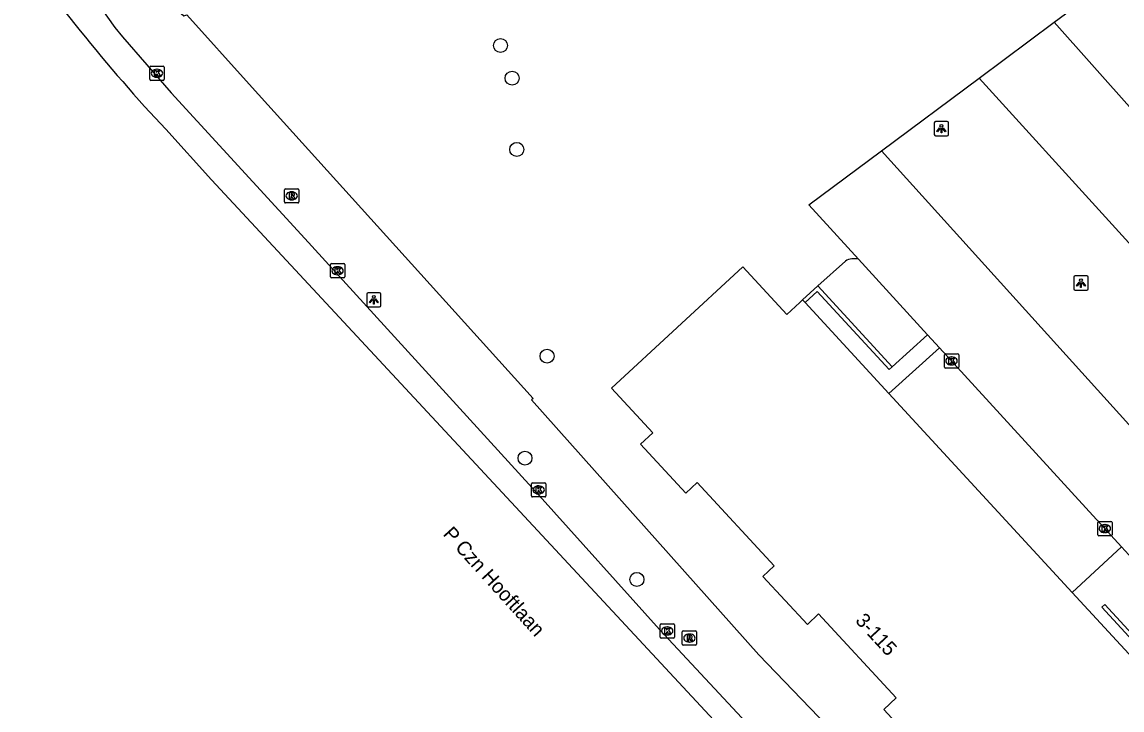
# Model space of a CAD drawing. Extents: x 161087 to 161922, y 382574 to 383873.
# Drawn here: x 161573.6 to 161650.7, y 382684.2 to 382732.3 of the extents above; entities that cross this region are included whole.
import ezdxf

# ---------------------------------------------------------------- set-up
doc = ezdxf.new("R2010")
doc.units = 0
for name, color, linetype in [('IMGEO_Boom', 7, 'Continuous'), ('IMGEO_Groenvoorziening', 7, 'Continuous'), ('IMGEO_Kolk', 7, 'Continuous'), ('IMGEO_Lichtpunt', 7, 'Continuous'), ('IMGEO_Muur', 7, 'Continuous'), ('IMGEO_Openbare_ruimte_label', 7, 'Continuous'), ('IMGEO_Pand', 7, 'Continuous'), ('IMGEO_Pand_nummerreeks', 7, 'Continuous'), ('IMGEO_Parkeervlak_open', 7, 'Continuous'), ('IMGEO_Rijbaan_lokaal_gesloten', 7, 'Continuous'), ('IMGEO_Rijbaan_lokaal_open', 7, 'Continuous'), ('IMGEO_Rioolput', 7, 'Continuous'), ('IMGEO_Voetpad_open', 7, 'Continuous')]:
    doc.layers.add(name, color=color, linetype=linetype)

msp = doc.modelspace()

# ---------------------------------------------------------------- linework, layer by layer
at = {"layer": 'IMGEO_Boom'}
for centre in [(161607.142, 382730.699), (161607.958, 382728.415), (161608.285, 382723.426), (161610.405, 382708.942), (161608.861, 382701.802), (161616.697, 382693.31)]:
    msp.add_circle(centre, 0.489, dxfattribs=at)
at = {"layer": 'IMGEO_Groenvoorziening'}
msp.add_lwpolyline([(161629.361, 382713.862), (161631.288, 382715.608)], dxfattribs=at)
msp.add_arc((161631.903, 382714.542), 1.231, 75.94681, 119.99733, dxfattribs=at)
at = {"layer": 'IMGEO_Kolk'}
for p, q in [((161582.598, 382728.335), (161582.598, 382729.187)), ((161582.673, 382729.261), (161583.525, 382729.261)), ((161583.599, 382729.187), (161583.599, 382728.335)), ((161583.109, 382728.481), (161583.084, 382728.481)), ((161583.086, 382729.041), (161583.111, 382729.041)), ((161583.525, 382728.261), (161582.673, 382728.261)), ((161595.241, 382714.502), (161595.241, 382715.354)), ((161595.316, 382715.428), (161596.168, 382715.428)), ((161595.729, 382715.208), (161595.754, 382715.208)), ((161596.242, 382715.354), (161596.242, 382714.502)), ((161595.752, 382714.648), (161595.727, 382714.648)), ((161596.168, 382714.428), (161595.316, 382714.428)), ((161638.294, 382709.109), (161639.146, 382709.109)), ((161638.219, 382708.183), (161638.219, 382709.035)), ((161638.73, 382708.329), (161638.705, 382708.329)), ((161638.707, 382708.889), (161638.732, 382708.889)), ((161639.22, 382709.035), (161639.22, 382708.183)), ((161639.146, 382708.109), (161638.294, 382708.109)), ((161609.316, 382699.156), (161609.316, 382700.008)), ((161609.391, 382700.082), (161610.243, 382700.082)), ((161609.804, 382699.862), (161609.829, 382699.862)), ((161610.317, 382700.008), (161610.317, 382699.156)), ((161610.243, 382699.082), (161609.391, 382699.082)), ((161609.827, 382699.302), (161609.802, 382699.302)), ((161648.954, 382696.443), (161648.954, 382697.295)), ((161649.029, 382697.369), (161649.881, 382697.369)), ((161649.442, 382697.149), (161649.467, 382697.149)), ((161649.955, 382697.295), (161649.955, 382696.443)), ((161649.881, 382696.369), (161649.029, 382696.369)), ((161649.465, 382696.589), (161649.44, 382696.589)), ((161618.319, 382689.273), (161618.319, 382690.125)), ((161618.394, 382690.199), (161619.246, 382690.199)), ((161618.807, 382689.979), (161618.832, 382689.979)), ((161619.32, 382690.125), (161619.32, 382689.273)), ((161619.246, 382689.199), (161618.394, 382689.199)), ((161618.83, 382689.419), (161618.805, 382689.419))]:
    msp.add_line(p, q, dxfattribs=at)
for points in [[(161582.598, 382728.335), (161582.598, 382729.187)], [(161582.673, 382729.261), (161583.525, 382729.261)], [(161583.599, 382729.187), (161583.599, 382728.335)], [(161582.919, 382728.961), (161583.042, 382728.961), (161583.042, 382728.81), (161583.172, 382728.961), (161583.336, 382728.961), (161583.19, 382728.81), (161583.343, 382728.561), (161583.191, 382728.561), (161583.106, 382728.725), (161583.042, 382728.658), (161583.042, 382728.561), (161582.919, 382728.561), (161582.919, 382728.961)], [(161583.525, 382728.261), (161582.673, 382728.261)], [(161595.241, 382714.502), (161595.241, 382715.354)], [(161595.316, 382715.428), (161596.168, 382715.428)], [(161596.242, 382715.354), (161596.242, 382714.502)], [(161595.562, 382715.128), (161595.685, 382715.128), (161595.685, 382714.977), (161595.815, 382715.128), (161595.979, 382715.128), (161595.833, 382714.977), (161595.986, 382714.728), (161595.834, 382714.728), (161595.749, 382714.892), (161595.685, 382714.825), (161595.685, 382714.728), (161595.562, 382714.728), (161595.562, 382715.128)], [(161596.168, 382714.428), (161595.316, 382714.428)], [(161638.294, 382709.109), (161639.146, 382709.109)], [(161638.219, 382708.183), (161638.219, 382709.035)], [(161638.54, 382708.809), (161638.663, 382708.809), (161638.663, 382708.658), (161638.793, 382708.809), (161638.957, 382708.809), (161638.811, 382708.658), (161638.964, 382708.409), (161638.812, 382708.409), (161638.727, 382708.573), (161638.663, 382708.506), (161638.663, 382708.409), (161638.54, 382708.409), (161638.54, 382708.809)], [(161639.22, 382709.035), (161639.22, 382708.183)], [(161639.146, 382708.109), (161638.294, 382708.109)], [(161609.316, 382699.156), (161609.316, 382700.008)], [(161609.391, 382700.082), (161610.243, 382700.082)], [(161610.317, 382700.008), (161610.317, 382699.156)], [(161610.243, 382699.082), (161609.391, 382699.082)], [(161609.637, 382699.782), (161609.76, 382699.782), (161609.76, 382699.631), (161609.89, 382699.782), (161610.054, 382699.782), (161609.908, 382699.631), (161610.061, 382699.382), (161609.909, 382699.382), (161609.824, 382699.546), (161609.76, 382699.479), (161609.76, 382699.382), (161609.637, 382699.382), (161609.637, 382699.782)], [(161648.954, 382696.443), (161648.954, 382697.295)], [(161649.029, 382697.369), (161649.881, 382697.369)], [(161649.275, 382697.069), (161649.398, 382697.069), (161649.398, 382696.918), (161649.528, 382697.069), (161649.692, 382697.069), (161649.546, 382696.918), (161649.699, 382696.669), (161649.547, 382696.669), (161649.462, 382696.833), (161649.398, 382696.766), (161649.398, 382696.669), (161649.275, 382696.669), (161649.275, 382697.069)], [(161649.955, 382697.295), (161649.955, 382696.443)], [(161649.881, 382696.369), (161649.029, 382696.369)], [(161618.319, 382689.273), (161618.319, 382690.125)], [(161618.394, 382690.199), (161619.246, 382690.199)], [(161618.64, 382689.899), (161618.763, 382689.899), (161618.763, 382689.748), (161618.893, 382689.899), (161619.057, 382689.899), (161618.911, 382689.748), (161619.064, 382689.499), (161618.912, 382689.499), (161618.827, 382689.663), (161618.763, 382689.596), (161618.763, 382689.499), (161618.64, 382689.499), (161618.64, 382689.899)], [(161619.32, 382690.125), (161619.32, 382689.273)], [(161619.246, 382689.199), (161618.394, 382689.199)]]:
    msp.add_lwpolyline(points, dxfattribs=at)
for centre, start, end in [((161582.675, 382729.185), 91.55205, 178.44795), ((161582.675, 382729.185), 91.55205, 178.44795), ((161583.523, 382729.185), 1.55205, 88.44795), ((161583.523, 382729.185), 1.55205, 88.44795), ((161582.675, 382728.337), 181.55205, 268.44795), ((161582.675, 382728.337), 181.55205, 268.44795), ((161583.523, 382728.337), 271.55205, 358.44795), ((161583.523, 382728.337), 271.55205, 358.44795), ((161595.318, 382715.352), 91.55205, 178.44795), ((161595.318, 382715.352), 91.55205, 178.44795), ((161596.166, 382715.352), 1.55205, 88.44795), ((161596.166, 382715.352), 1.55205, 88.44795), ((161595.318, 382714.504), 181.55205, 268.44795), ((161595.318, 382714.504), 181.55205, 268.44795), ((161596.166, 382714.504), 271.55205, 358.44795), ((161596.166, 382714.504), 271.55205, 358.44795), ((161638.296, 382709.033), 91.55205, 178.44795), ((161638.296, 382709.033), 91.55205, 178.44795), ((161639.144, 382709.033), 1.55205, 88.44795), ((161639.144, 382709.033), 1.55205, 88.44795), ((161638.296, 382708.185), 181.55205, 268.44795), ((161638.296, 382708.185), 181.55205, 268.44795), ((161639.144, 382708.185), 271.55205, 358.44795), ((161639.144, 382708.185), 271.55205, 358.44795), ((161609.393, 382700.006), 91.55205, 178.44795), ((161609.393, 382700.006), 91.55205, 178.44795), ((161610.241, 382700.006), 1.55205, 88.44795), ((161610.241, 382700.006), 1.55205, 88.44795), ((161609.393, 382699.158), 181.55205, 268.44795), ((161609.393, 382699.158), 181.55205, 268.44795), ((161610.241, 382699.158), 271.55205, 358.44795), ((161610.241, 382699.158), 271.55205, 358.44795), ((161649.031, 382697.293), 91.55205, 178.44795), ((161649.031, 382697.293), 91.55205, 178.44795), ((161649.879, 382697.293), 1.55205, 88.44795), ((161649.879, 382697.293), 1.55205, 88.44795), ((161649.031, 382696.445), 181.55205, 268.44795), ((161649.031, 382696.445), 181.55205, 268.44795), ((161649.879, 382696.445), 271.55205, 358.44795), ((161649.879, 382696.445), 271.55205, 358.44795), ((161618.396, 382690.123), 91.55205, 178.44795), ((161618.396, 382690.123), 91.55205, 178.44795), ((161619.244, 382690.123), 1.55205, 88.44795), ((161619.244, 382690.123), 1.55205, 88.44795), ((161618.396, 382689.275), 181.55205, 268.44795), ((161618.396, 382689.275), 181.55205, 268.44795), ((161619.244, 382689.275), 271.55205, 358.44795), ((161619.244, 382689.275), 271.55205, 358.44795)]:
    msp.add_arc(centre, 0.0765, start, end, dxfattribs=at)
for centre, major_axis, ratio, start_param, end_param in [((161583.085, 382728.761), (-0.387, 0.002), 0.722429, 4.712389, 7.853982), ((161583.11, 382728.761), (-0.39, 0.002), 0.717154, 1.570796, 4.712389), ((161595.728, 382714.928), (-0.387, 0.002), 0.722429, 4.712389, 7.853982), ((161595.753, 382714.928), (-0.39, 0.002), 0.717154, 1.570796, 4.712389), ((161638.706, 382708.609), (-0.387, 0.002), 0.722429, 4.712389, 7.853982), ((161638.731, 382708.609), (-0.39, 0.002), 0.717154, 1.570796, 4.712389), ((161609.803, 382699.582), (-0.387, 0.002), 0.722429, 4.712389, 7.853982), ((161609.828, 382699.582), (-0.39, 0.002), 0.717154, 1.570796, 4.712389), ((161649.441, 382696.869), (-0.387, 0.002), 0.722429, 4.712389, 7.853982), ((161649.466, 382696.869), (-0.39, 0.002), 0.717154, 1.570796, 4.712389), ((161618.806, 382689.699), (-0.387, 0.002), 0.722429, 4.712389, 7.853982), ((161618.831, 382689.699), (-0.39, 0.002), 0.717154, 1.570796, 4.712389)]:
    msp.add_ellipse(centre, major_axis=major_axis, ratio=ratio, start_param=start_param, end_param=end_param, dxfattribs=at)
at = {"layer": 'IMGEO_Lichtpunt'}
for p, q in [((161637.513, 382725.282), (161637.513, 382724.475)), ((161637.513, 382725.282), (161637.513, 382724.475)), ((161638.415, 382725.377), (161637.607, 382725.377)), ((161638.415, 382725.377), (161637.607, 382725.377)), ((161638.509, 382724.475), (161638.509, 382725.282)), ((161638.509, 382724.475), (161638.509, 382725.282)), ((161637.607, 382724.381), (161638.415, 382724.381)), ((161637.607, 382724.381), (161638.415, 382724.381)), ((161647.282, 382714.47), (161647.282, 382713.663)), ((161647.282, 382714.47), (161647.282, 382713.663)), ((161648.184, 382714.565), (161647.376, 382714.565)), ((161648.184, 382714.565), (161647.376, 382714.565)), ((161648.278, 382713.663), (161648.278, 382714.47)), ((161648.278, 382713.663), (161648.278, 382714.47)), ((161597.782, 382713.296), (161597.782, 382712.489)), ((161597.782, 382713.296), (161597.782, 382712.489)), ((161598.684, 382713.391), (161597.876, 382713.391)), ((161598.684, 382713.391), (161597.876, 382713.391)), ((161598.778, 382712.489), (161598.778, 382713.296)), ((161598.778, 382712.489), (161598.778, 382713.296)), ((161647.376, 382713.569), (161648.184, 382713.569)), ((161647.376, 382713.569), (161648.184, 382713.569)), ((161597.876, 382712.395), (161598.684, 382712.395)), ((161597.876, 382712.395), (161598.684, 382712.395))]:
    msp.add_line(p, q, dxfattribs=at)
for points in [[(161637.887, 382724.946), (161637.926, 382724.918), (161637.738, 382724.656), (161637.7, 382724.683), (161637.887, 382724.946)], [(161637.989, 382724.898), (161638.036, 382724.898), (161638.036, 382724.576), (161637.989, 382724.576), (161637.989, 382724.898)], [(161638.099, 382724.918), (161638.137, 382724.945), (161638.324, 382724.683), (161638.285, 382724.655), (161638.099, 382724.918)], [(161647.656, 382714.134), (161647.695, 382714.106), (161647.507, 382713.844), (161647.469, 382713.871), (161647.656, 382714.134)], [(161647.758, 382714.086), (161647.805, 382714.086), (161647.805, 382713.764), (161647.758, 382713.764), (161647.758, 382714.086)], [(161647.868, 382714.106), (161647.906, 382714.133), (161648.093, 382713.871), (161648.054, 382713.843), (161647.868, 382714.106)], [(161598.156, 382712.96), (161598.195, 382712.932), (161598.007, 382712.67), (161597.969, 382712.697), (161598.156, 382712.96)], [(161598.258, 382712.912), (161598.305, 382712.912), (161598.305, 382712.59), (161598.258, 382712.59), (161598.258, 382712.912)], [(161598.368, 382712.932), (161598.406, 382712.959), (161598.593, 382712.697), (161598.554, 382712.669), (161598.368, 382712.932)]]:
    msp.add_lwpolyline(points, dxfattribs=at)
for centre in [(161638.012, 382725.08), (161647.781, 382714.268), (161598.281, 382713.094)]:
    msp.add_circle(centre, 0.0994, dxfattribs=at)
for centre, start, end in [((161637.607, 382725.282), 90, 180), ((161637.607, 382725.282), 90, 180), ((161638.415, 382725.282), 0, 90), ((161638.415, 382725.282), 0, 90), ((161637.607, 382724.475), 180, 270), ((161637.607, 382724.475), 180, 270), ((161638.415, 382724.475), 270, 0), ((161638.415, 382724.475), 270, 360), ((161647.376, 382714.47), 90, 180), ((161647.376, 382714.47), 90, 180), ((161648.184, 382714.47), 0, 90), ((161648.184, 382714.47), 0, 90), ((161647.376, 382713.663), 180, 270), ((161647.376, 382713.663), 180, 270), ((161648.184, 382713.663), 270, 0), ((161648.184, 382713.663), 270, 360), ((161597.876, 382713.296), 90, 180), ((161597.876, 382713.296), 90, 180), ((161598.684, 382713.296), 0, 90), ((161598.684, 382713.296), 0, 90), ((161597.876, 382712.489), 180, 270), ((161597.876, 382712.489), 180, 270), ((161598.684, 382712.489), 270, 0), ((161598.684, 382712.489), 270, 360)]:
    msp.add_arc(centre, 0.0946, start, end, dxfattribs=at)
at = {"layer": 'IMGEO_Muur'}
for points in [[(161628.297, 382712.881), (161629.361, 382713.862)], [(161629.361, 382713.862), (161634.574, 382708.203)], [(161634.574, 382708.203), (161634.359, 382708.005), (161629.313, 382713.483), (161628.463, 382712.7)], [(161654.648, 382685.492), (161649.237, 382691.365), (161649.445, 382691.558), (161654.886, 382685.652)]]:
    msp.add_lwpolyline(points, dxfattribs=at)
at = {"layer": 'IMGEO_Pand'}
for points in [[(161637.133, 382680.802), (161633.986, 382684.208), (161634.853, 382685.008), (161629.418, 382690.891), (161628.626, 382690.16), (161625.521, 382693.521), (161626.311, 382694.251), (161620.913, 382700.093), (161620.113, 382699.354), (161616.946, 382702.781), (161617.802, 382703.572), (161614.909, 382706.703), (161624.113, 382715.206), (161627.197, 382711.868), (161628.092, 382712.692), (161628.297, 382712.881)], [(161628.463, 382712.7), (161628.297, 382712.881)], [(161634.338, 382706.324), (161628.463, 382712.7)], [(161647.175, 382692.39), (161634.338, 382706.324)], [(161654.648, 382685.492), (161653.956, 382685.031), (161647.175, 382692.39)]]:
    msp.add_lwpolyline(points, dxfattribs=at)
at = {"layer": 'IMGEO_Parkeervlak_open'}
for points in [[(161645.915, 382732.339), (161650.055, 382735.423), (161652.164, 382733.056), (161661.072, 382722.472), (161675.692, 382731.244), (161680.06, 382733.622), (161682.663, 382729.735)], [(161633.825, 382723.334), (161640.645, 382728.413)]]:
    msp.add_lwpolyline(points, dxfattribs=at)
at = {"layer": 'IMGEO_Rijbaan_lokaal_gesloten'}
for points in [[(161578.104, 382734.877), (161580.138, 382731.973), (161580.691, 382731.313), (161584.083, 382727.396), (161593.448, 382717.185), (161609.858, 382699.184), (161618.288, 382689.808), (161627.567, 382679.823), (161637.265, 382669.796), (161642.351, 382664.758), (161645.804, 382661.238)], [(161709.816, 382586.053), (161680.185, 382618.886), (161643.825, 382659.427), (161627.635, 382677.479), (161586.909, 382721.287), (161583.729, 382724.844), (161582.233, 382726.427)]]:
    msp.add_lwpolyline(points, dxfattribs=at)
msp.add_arc((161683.305, 382816.893), 135.645, 217.90373, 221.83054, dxfattribs=at)
at = {"layer": 'IMGEO_Rijbaan_lokaal_open'}
for points in [[(161640.645, 382728.413), (161645.915, 382732.339)], [(161682.663, 382729.735), (161659.826, 382716.672), (161645.915, 382732.339)], [(161640.645, 382728.413), (161658.818, 382708.421)], [(161632.202, 382715.736), (161628.729, 382719.538), (161633.825, 382723.334)], [(161660.241, 382707.326), (161682.173, 382721.921), (161686.783, 382714.893), (161656.868, 382694.863), (161654.688, 382698.482), (161655.434, 382699.108), (161652.223, 382702.935), (161633.825, 382723.334)], [(161632.202, 382715.736), (161637.045, 382710.44)], [(161637.045, 382710.44), (161637.868, 382709.539)], [(161637.868, 382709.539), (161650.622, 382695.592)], [(161650.622, 382695.592), (161652.162, 382693.908)]]:
    msp.add_lwpolyline(points, dxfattribs=at)
at = {"layer": 'IMGEO_Rioolput'}
for p, q in [((161592.026, 382719.747), (161592.026, 382720.599)), ((161592.101, 382720.673), (161592.953, 382720.673)), ((161593.027, 382720.599), (161593.027, 382719.747)), ((161592.537, 382719.893), (161592.512, 382719.893)), ((161592.514, 382720.453), (161592.539, 382720.453)), ((161592.953, 382719.673), (161592.101, 382719.673)), ((161619.87, 382688.777), (161619.87, 382689.629)), ((161619.945, 382689.703), (161620.797, 382689.703)), ((161620.358, 382689.483), (161620.383, 382689.483)), ((161620.871, 382689.629), (161620.871, 382688.777)), ((161620.797, 382688.703), (161619.945, 382688.703)), ((161620.381, 382688.923), (161620.356, 382688.923))]:
    msp.add_line(p, q, dxfattribs=at)
for points in [[(161592.026, 382719.747), (161592.026, 382720.599)], [(161592.101, 382720.673), (161592.953, 382720.673)], [(161593.027, 382720.599), (161593.027, 382719.747)], [(161592.615, 382720.371), (161592.363, 382720.373), (161592.363, 382719.973)], [(161592.363, 382719.973), (161592.487, 382719.973), (161592.487, 382720.135), (161592.498, 382720.135)], [(161592.541, 382720.292), (161592.487, 382720.292), (161592.487, 382720.211)], [(161592.487, 382720.211), (161592.539, 382720.211)], [(161592.545, 382720.106), (161592.616, 382719.973), (161592.756, 382719.973), (161592.691, 382720.099)], [(161592.953, 382719.673), (161592.101, 382719.673)], [(161619.87, 382688.777), (161619.87, 382689.629)], [(161619.945, 382689.703), (161620.797, 382689.703)], [(161620.459, 382689.401), (161620.207, 382689.403), (161620.207, 382689.003)], [(161620.207, 382689.003), (161620.331, 382689.003), (161620.331, 382689.165), (161620.342, 382689.165)], [(161620.385, 382689.322), (161620.331, 382689.322), (161620.331, 382689.241)], [(161620.331, 382689.241), (161620.383, 382689.241)], [(161620.389, 382689.136), (161620.46, 382689.003), (161620.6, 382689.003), (161620.535, 382689.129)], [(161620.871, 382689.629), (161620.871, 382688.777)], [(161620.797, 382688.703), (161619.945, 382688.703)]]:
    msp.add_lwpolyline(points, dxfattribs=at)
for centre, radius, start, end in [((161592.103, 382720.597), 0.0765, 91.55205, 178.44795), ((161592.103, 382720.597), 0.0765, 91.55205, 178.44795), ((161592.951, 382720.597), 0.0765, 1.55205, 88.44795), ((161592.951, 382720.597), 0.0765, 1.55205, 88.44795), ((161592.497, 382720.082), 0.0533, 26.02933, 88.69889), ((161592.523, 382720.4), 0.19, 274.7715, 282.96867), ((161592.547, 382720.196), 0.0964, 77.00612, 93.18647), ((161592.561, 382720.253), 0.0378, 276.66336, 79.67722), ((161592.614, 382720.261), 0.109, 350.36119, 89.41601), ((161592.612, 382720.261), 0.112, 277.58423, 350.98172), ((161592.596, 382720.046), 0.108, 29.51342, 73.79051), ((161592.103, 382719.749), 0.0765, 181.55205, 268.44795), ((161592.103, 382719.749), 0.0765, 181.55205, 268.44795), ((161592.951, 382719.749), 0.0765, 271.55205, 358.44795), ((161592.951, 382719.749), 0.0765, 271.55205, 358.44795), ((161619.947, 382689.627), 0.0765, 91.55205, 178.44795), ((161619.947, 382689.627), 0.0765, 91.55205, 178.44795), ((161620.341, 382689.112), 0.0533, 26.02933, 88.69889), ((161620.367, 382689.43), 0.19, 274.7715, 282.96867), ((161620.391, 382689.226), 0.0964, 77.00612, 93.18647), ((161620.405, 382689.283), 0.0378, 276.66336, 79.67722), ((161620.458, 382689.291), 0.109, 350.36119, 89.41601), ((161620.456, 382689.291), 0.112, 277.58423, 350.98172), ((161620.44, 382689.076), 0.108, 29.51342, 73.79051), ((161620.795, 382689.627), 0.0765, 1.55205, 88.44795), ((161620.795, 382689.627), 0.0765, 1.55205, 88.44795), ((161619.947, 382688.779), 0.0765, 181.55205, 268.44795), ((161619.947, 382688.779), 0.0765, 181.55205, 268.44795), ((161620.795, 382688.779), 0.0765, 271.55205, 358.44795), ((161620.795, 382688.779), 0.0765, 271.55205, 358.44795)]:
    msp.add_arc(centre, radius, start, end, dxfattribs=at)
for centre, major_axis, ratio, start_param, end_param in [((161592.513, 382720.173), (-0.387, 0.002), 0.722429, 4.712389, 7.853982), ((161592.538, 382720.173), (-0.39, 0.002), 0.717154, 1.570796, 4.712389), ((161620.357, 382689.203), (-0.387, 0.002), 0.722429, 4.712389, 7.853982), ((161620.382, 382689.203), (-0.39, 0.002), 0.717154, 1.570796, 4.712389)]:
    msp.add_ellipse(centre, major_axis=major_axis, ratio=ratio, start_param=start_param, end_param=end_param, dxfattribs=at)
at = {"layer": 'IMGEO_Voetpad_open'}
for points in [[(161573.649, 382745.916), (161575.439, 382743.417), (161575.924, 382742.835), (161583.433, 382734.169), (161584.982, 382732.778), (161585.192, 382732.858), (161589.562, 382727.999), (161609.424, 382705.975), (161609.305, 382705.895), (161625.238, 382688.024), (161643.165, 382669.38), (161647.852, 382664.262), (161649.374, 382662.6)], [(161634.574, 382708.203), (161637.045, 382710.44)], [(161634.338, 382706.324), (161637.868, 382709.539)], [(161650.622, 382695.592), (161647.175, 382692.39)]]:
    msp.add_lwpolyline(points, dxfattribs=at)

# ---------------------------------------------------------------- texts
at = {"layer": 'IMGEO_Openbare_ruimte_label'}
msp.add_text('P Czn Hooftlaan', height=1, rotation=312.12344, dxfattribs=at).set_placement((161603.067, 382696.449))
at = {"layer": 'IMGEO_Pand_nummerreeks'}
msp.add_text('3-115', height=1, rotation=312.73098, dxfattribs=at).set_placement((161631.933, 382690.38))

doc.saveas('drawing.dxf')
